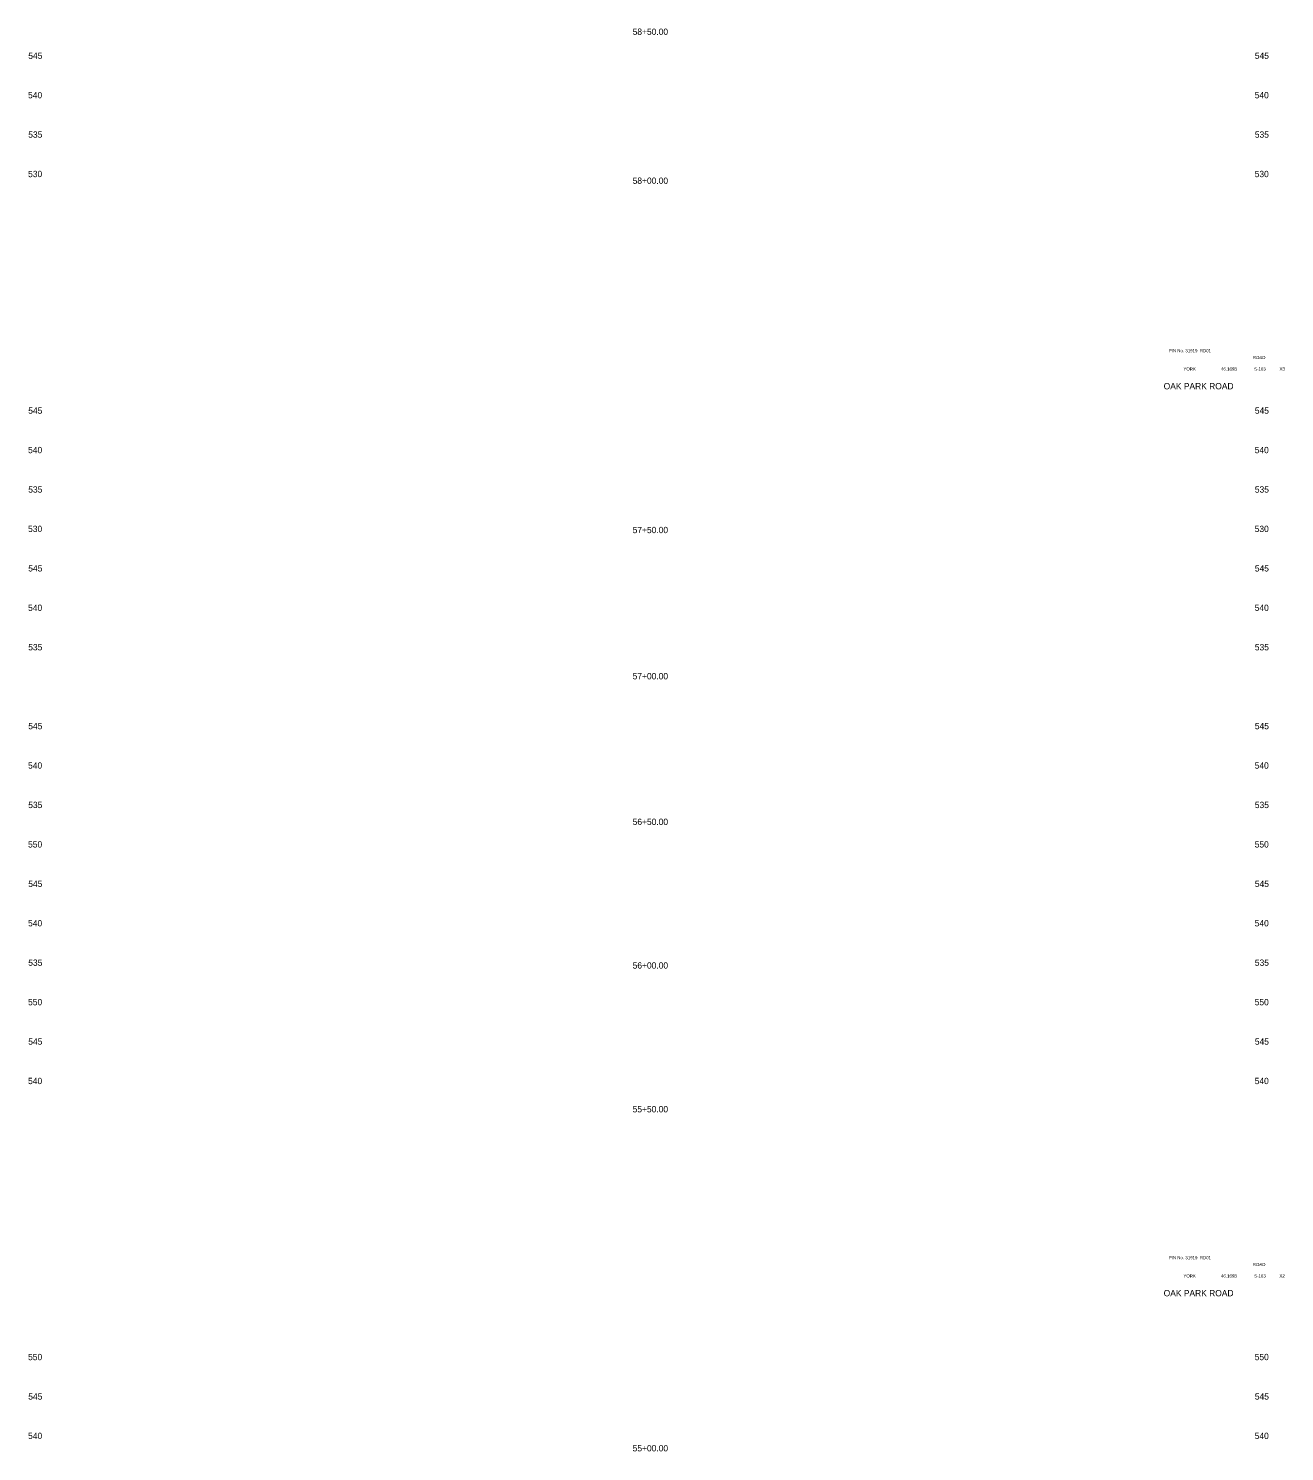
# Model space of a CAD drawing. Extents: x 1001 to 1161, y 1007 to 2483.
# Drawn here: x 1001.2 to 1160.4, y 1193.4 to 1373.9 of the extents above; entities that cross this region are included whole.
import ezdxf

# ---------------------------------------------------------------- set-up
doc = ezdxf.new("R2010")
doc.units = 0
for name, color, linetype in [('RD_GPK_XS_Cell', 7, 'Continuous'), ('RD_SHT_TX', 7, 'Continuous'), ('RD_XS_ExGround', 7, 'Continuous')]:
    doc.layers.add(name, color=color, linetype=linetype)

msp = doc.modelspace()

# ---------------------------------------------------------------- texts
at = {"layer": 'RD_GPK_XS_Cell'}
for s, p in [('545', (1001.16, 1370)), ('545', (1156.66, 1370)), ('540', (1001.14, 1365)), ('540', (1156.64, 1365)), ('535', (1001.16, 1360)), ('535', (1156.66, 1360)), ('530', (1001.14, 1355)), ('530', (1156.64, 1355)), ('545', (1001.16, 1325)), ('545', (1156.66, 1325)), ('540', (1001.14, 1320)), ('540', (1156.64, 1320)), ('535', (1001.16, 1315)), ('535', (1156.66, 1315)), ('530', (1001.14, 1310)), ('530', (1156.64, 1310)), ('545', (1001.16, 1305)), ('545', (1156.66, 1305)), ('540', (1001.14, 1300)), ('540', (1156.64, 1300)), ('535', (1001.16, 1295)), ('535', (1156.66, 1295)), ('545', (1001.16, 1285)), ('545', (1156.66, 1285)), ('540', (1001.14, 1280)), ('540', (1156.64, 1280)), ('535', (1001.16, 1275)), ('535', (1156.66, 1275)), ('550', (1001.14, 1270)), ('550', (1156.64, 1270)), ('545', (1001.16, 1265)), ('545', (1156.66, 1265)), ('540', (1001.14, 1260)), ('540', (1156.64, 1260)), ('535', (1001.16, 1255)), ('535', (1156.66, 1255)), ('550', (1001.14, 1250)), ('550', (1156.64, 1250)), ('545', (1001.16, 1245)), ('545', (1156.66, 1245)), ('540', (1001.14, 1240)), ('540', (1156.64, 1240)), ('550', (1001.14, 1205)), ('550', (1156.64, 1205)), ('545', (1001.16, 1200)), ('545', (1156.66, 1200)), ('540', (1001.14, 1195)), ('540', (1156.64, 1195))]:
    msp.add_text(s, height=0.8, dxfattribs=at).set_placement(p)
at = {"layer": 'RD_SHT_TX'}
for s, height, p in [('PIN No. 31919_RD01', 0.4, (1145.76, 1332.8)), ('ROAD', 0.4, (1156.41, 1331.93)), ('YORK', 0.4, (1147.61, 1330.48)), ('46.169B', 0.4, (1152.37, 1330.48)), ('S-103', 0.4, (1156.57, 1330.48)), ('X3', 0.4, (1159.79, 1330.48)), ('OAK PARK ROAD', 0.8, (1145.1, 1328.1)), ('PIN No. 31919_RD01', 0.4, (1145.76, 1217.8)), ('ROAD', 0.4, (1156.41, 1216.93)), ('YORK', 0.4, (1147.61, 1215.48)), ('46.169B', 0.4, (1152.37, 1215.48)), ('S-103', 0.4, (1156.57, 1215.48)), ('X2', 0.4, (1159.78, 1215.48)), ('OAK PARK ROAD', 0.8, (1145.1, 1213.1))]:
    msp.add_text(s, height=height, dxfattribs=at).set_placement(p)
at = {"layer": 'RD_XS_ExGround'}
for s, p in [('58+50.00', (1077.78, 1373.04)), ('58+00.00', (1077.78, 1354.15)), ('57+50.00', (1077.78, 1309.86)), ('57+00.00', (1077.78, 1291.33)), ('56+50.00', (1077.78, 1272.86)), ('56+00.00', (1077.78, 1254.65)), ('55+50.00', (1077.78, 1236.42)), ('55+00.00', (1077.78, 1193.43))]:
    msp.add_text(s, height=0.8, dxfattribs=at).set_placement(p)

doc.saveas('drawing.dxf')
